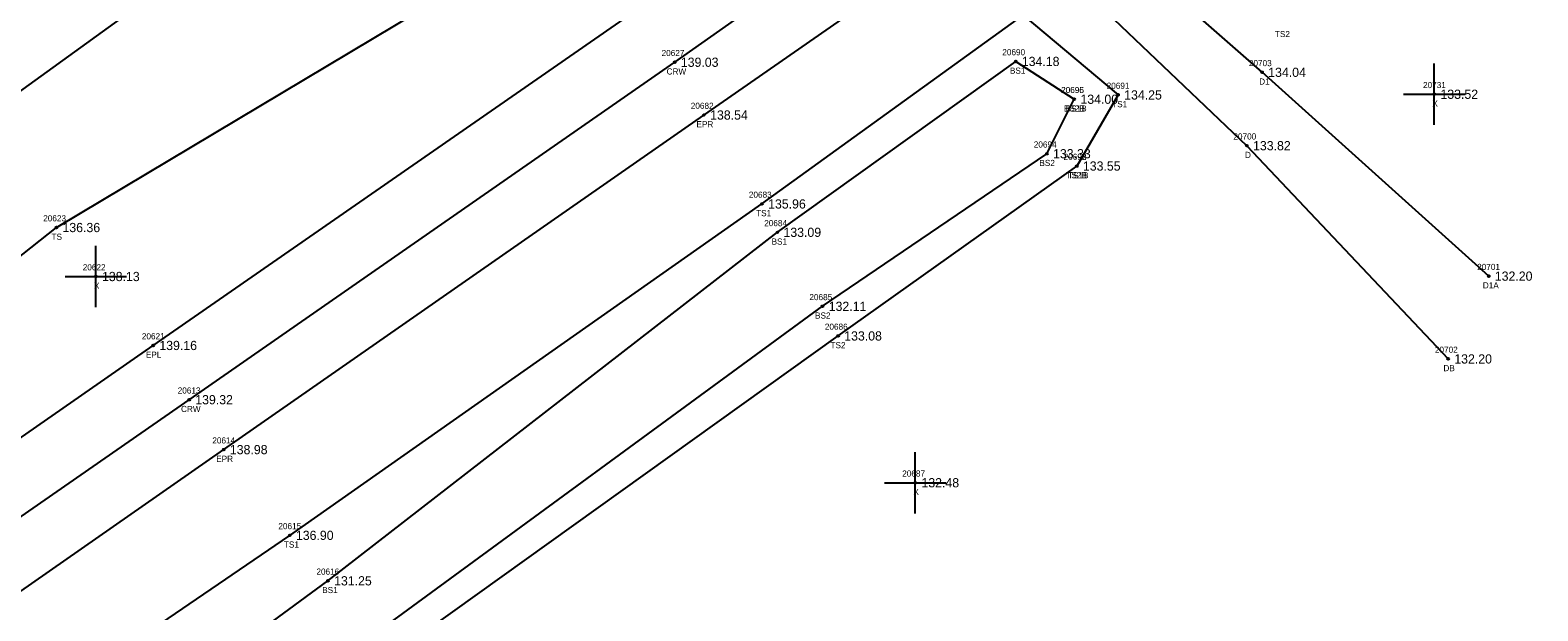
# Model space of a CAD drawing. Extents: x 2449605 to 2452431, y 1012876 to 1014922.
# Drawn here: x 2451655.9 to 2451901.5, y 1014341.9 to 1014436.4 of the extents above; entities that cross this region are included whole.
import ezdxf

# ---------------------------------------------------------------- set-up
doc = ezdxf.new("R2010")
doc.units = 0
for name, color, linetype in [('RD_DTM_BkLn1', 7, 'Continuous'), ('RD_DTM_BkLn2', 7, 'Continuous'), ('RD_DTM_BkLn_txCode', 7, 'Continuous'), ('RD_EX_Driveway', 7, 'Continuous'), ('RD_EX_Driveway_txCode', 7, 'Continuous'), ('RD_EX_Misc', 7, 'Continuous'), ('RD_EX_Misc_txCode', 7, 'Continuous'), ('RD_EX_Road', 7, 'Continuous'), ('RD_EX_Road_txCode', 7, 'Continuous'), ('RD_EX_TX_Driveway_ELEV', 7, 'Continuous'), ('RD_EX_TX_Misc_ELEV', 7, 'Continuous'), ('RD_EX_TX_Road_ELEV', 7, 'Continuous'), ('RD_HC_Survey_ELEV', 7, 'Continuous'), ('RD_HC_Survey_txCode', 7, 'Continuous'), ('RD_SMD_Locator', 7, 'Continuous')]:
    doc.layers.add(name, color=color, linetype=linetype)

msp = doc.modelspace()

# ---------------------------------------------------------------- linework, layer by layer
at = {"layer": 'RD_DTM_BkLn1'}
msp.add_lwpolyline([(2451118.89, 1013985.11), (2451203.66, 1014044.04), (2451282.83, 1014099.78), (2451359.44, 1014152.74), (2451440.83, 1014209.36), (2451521.56, 1014265.18), (2451601.57, 1014320.62), (2451681.76, 1014376.26), (2451760.87, 1014431.18), (2451838.81, 1014486.02), (2451917.14, 1014540.46), (2451997.53, 1014596.52), (2452078.1, 1014652.75), (2452159.13, 1014709.2), (2452240.28, 1014765.75), (2452322.88, 1014822.76), (2452350.66, 1014841.92)], dxfattribs=at)
at = {"layer": 'RD_DTM_BkLn2'}
for points in [[(2451646.62, 1014421.01), (2451727.98, 1014479.74), (2451737.36, 1014488.81), (2451748.87, 1014487.34), (2451780.97, 1014516.03), (2451800.08, 1014516.09), (2451808.87, 1014514.25), (2451815.19, 1014518.52), (2451893.94, 1014584.77), (2451968.95, 1014641.82), (2452055.92, 1014696.27), (2452133.42, 1014744.91), (2452217.68, 1014799.33), (2452300.38, 1014857.1), (2452325.49, 1014877.68)], [(2451585.42, 1014345.19), (2451660.13, 1014404.28), (2451733.72, 1014448.23), (2451745.11, 1014454.23), (2451764.12, 1014467.91), (2451768.27, 1014469.92), (2451766.55, 1014486.31), (2451774.07, 1014492.64), (2451778.81, 1014490.13), (2451790.61, 1014483.42), (2451801.96, 1014488.52), (2451805.7, 1014492.48), (2451808.19, 1014504.09), (2451819.08, 1014511.44), (2451904.04, 1014564.11), (2451984.51, 1014617.35), (2452065.76, 1014673.28), (2452142.48, 1014732.95), (2452225.73, 1014787.51), (2452309.72, 1014842.9), (2452337.15, 1014861.43)], [(2451122.2, 1013975.67), (2451126.64, 1013971.77), (2451133.91, 1013974.2), (2451213.29, 1014028.58), (2451297.97, 1014080.75), (2451370.59, 1014133.41), (2451455.73, 1014187.81), (2451537.96, 1014241.24), (2451616.44, 1014298.53), (2451698.16, 1014354.19), (2451775.09, 1014408.12), (2451817.62, 1014438.82), (2451833.1, 1014425.86), (2451826.37, 1014414.29)], [(2451136.08, 1013956.85), (2451223.22, 1014008.35), (2451307.68, 1014070.02), (2451383.47, 1014112.6), (2451463.99, 1014176.33), (2451545.36, 1014231.17), (2451624.01, 1014287.82), (2451704.38, 1014346.79), (2451777.59, 1014403.5), (2451816.42, 1014431.31), (2451825.97, 1014425.16)], [(2451414.14, 1014133.11), (2451434.24, 1014145.95), (2451469.57, 1014168.89), (2451548.61, 1014225.27), (2451628.95, 1014281.61), (2451710.51, 1014337.03), (2451784.96, 1014391.46), (2451821.51, 1014416.29), (2451825.97, 1014425.16)], [(2451414.14, 1014133.11), (2451438.11, 1014142.38), (2451471.43, 1014164.27), (2451550.48, 1014222.82), (2451631.22, 1014277.79), (2451713.04, 1014333.4), (2451787.49, 1014386.64), (2451826.37, 1014414.29)]]:
    msp.add_lwpolyline(points, dxfattribs=at)
at = {"layer": 'RD_EX_Driveway'}
for points in [[(2451893.48, 1014396.37), (2451856.56, 1014429.54), (2451835.71, 1014447.82), (2451825.17, 1014464.13)], [(2451815.07, 1014456.96), (2451825.59, 1014444.74), (2451854.09, 1014417.6), (2451886.88, 1014382.9)]]:
    msp.add_lwpolyline(points, dxfattribs=at)
at = {"layer": 'RD_EX_Misc'}
for p, q in [((2451884.62, 1014420.97), (2451884.62, 1014430.97)), ((2451879.62, 1014425.97), (2451889.62, 1014425.97)), ((2451666.57, 1014391.31), (2451666.57, 1014401.31)), ((2451661.57, 1014396.31), (2451671.57, 1014396.31)), ((2451800.07, 1014357.75), (2451800.07, 1014367.75)), ((2451795.07, 1014362.75), (2451805.07, 1014362.75))]:
    msp.add_line(p, q, dxfattribs=at)
at = {"layer": 'RD_EX_Road'}
for points in [[(2451113.37, 1013993.22), (2451114.95, 1013995.06), (2451198.45, 1014053.46), (2451277.07, 1014108.71), (2451354.65, 1014162.03), (2451438.1, 1014219.98), (2451516.17, 1014274.12), (2451595.76, 1014329.36), (2451675.91, 1014385.09), (2451754.57, 1014439.6), (2451832.18, 1014494.6), (2451911.27, 1014549.31), (2451991.99, 1014605.1), (2452071.96, 1014661.47), (2452153.31, 1014717.5), (2452234.82, 1014774.14), (2452317.24, 1014831.48), (2452344.94, 1014850.58)], [(2451124.98, 1013977.04), (2451208.96, 1014035.6), (2451289.19, 1014091.86), (2451364.64, 1014143.97), (2451446.58, 1014201.16), (2451526.53, 1014256.42), (2451607.39, 1014312.42), (2451687.4, 1014368.14), (2451765.64, 1014422.59), (2451815.07, 1014456.96), (2451825.17, 1014464.13), (2451844.11, 1014477.45), (2451922.22, 1014531.75), (2452002.87, 1014588.1), (2452083.85, 1014644.47), (2452165.65, 1014701.19), (2452246.96, 1014757.82), (2452328.43, 1014814.34), (2452355.9, 1014833.22)]]:
    msp.add_lwpolyline(points, dxfattribs=at)
at = {"layer": 'RD_SMD_Locator'}
for centre in [(2451760.87, 1014431.18), (2451816.42, 1014431.31), (2451856.56, 1014429.54), (2451825.97, 1014425.16), (2451825.97, 1014425.16), (2451833.1, 1014425.86), (2451884.62, 1014425.97), (2451765.64, 1014422.59), (2451854.09, 1014417.6), (2451821.51, 1014416.29), (2451826.37, 1014414.29), (2451826.37, 1014414.29), (2451775.09, 1014408.12), (2451660.13, 1014404.28), (2451777.59, 1014403.5), (2451666.57, 1014396.31), (2451893.48, 1014396.37), (2451784.96, 1014391.46), (2451675.91, 1014385.09), (2451787.49, 1014386.64), (2451886.88, 1014382.9), (2451681.76, 1014376.26), (2451687.4, 1014368.14), (2451800.07, 1014362.75), (2451698.16, 1014354.19), (2451704.38, 1014346.79)]:
    msp.add_circle(centre, 0.15, dxfattribs=at)

# ---------------------------------------------------------------- texts
at = {"layer": 'RD_DTM_BkLn_txCode'}
for s, p in [('TS2', (2451858.65, 1014435.27)), ('20690', (2451814.24, 1014432.31)), ('BS1', (2451815.48, 1014429.31)), ('20696', (2451823.81, 1014426.16)), ('20695', (2451823.83, 1014426.16)), ('20691', (2451831.24, 1014426.86)), ('TS1', (2451832.14, 1014423.86)), ('BS2B', (2451824.27, 1014423.16)), ('BS1B', (2451824.56, 1014423.16)), ('20694', (2451819.37, 1014417.29)), ('BS2', (2451820.28, 1014414.29)), ('20692', (2451824.23, 1014415.29)), ('20693', (2451824.23, 1014415.29)), ('TS2B', (2451824.65, 1014412.29)), ('TS1B', (2451824.94, 1014412.29)), ('20683', (2451772.95, 1014409.12)), ('20623', (2451657.99, 1014405.28)), ('TS1', (2451774.13, 1014406.12)), ('20684', (2451775.45, 1014404.5)), ('TS', (2451659.34, 1014402.28)), ('BS1', (2451776.65, 1014401.5)), ('20685', (2451782.81, 1014392.46)), ('BS2', (2451783.73, 1014389.46)), ('20686', (2451785.33, 1014387.64)), ('TS2', (2451786.25, 1014384.64)), ('20615', (2451696.3, 1014355.19)), ('TS1', (2451697.2, 1014352.19)), ('20616', (2451702.5, 1014347.79)), ('BS1', (2451703.44, 1014344.79))]:
    msp.add_text(s, height=1, dxfattribs=at).set_placement(p)
at = {"layer": 'RD_EX_Driveway_txCode'}
for s, p in [('20703', (2451854.41, 1014430.54)), ('D1', (2451856.09, 1014427.54)), ('20700', (2451851.89, 1014418.6)), ('D', (2451853.78, 1014415.6)), ('20701', (2451891.6, 1014397.37)), ('D1A', (2451892.52, 1014394.37)), ('20702', (2451884.72, 1014383.9)), ('DB', (2451886.1, 1014380.9))]:
    msp.add_text(s, height=1, dxfattribs=at).set_placement(p)
at = {"layer": 'RD_EX_Misc_txCode'}
for s, p in [('20731', (2451882.78, 1014426.97)), ('X', (2451884.3, 1014423.97)), ('20622', (2451664.43, 1014397.31)), ('X', (2451666.26, 1014394.31)), ('20687', (2451797.93, 1014363.75)), ('X', (2451799.76, 1014360.75))]:
    msp.add_text(s, height=1, dxfattribs=at).set_placement(p)
at = {"layer": 'RD_EX_Road_txCode'}
for s, p in [('20682', (2451763.49, 1014423.59)), ('EPR', (2451764.41, 1014420.59)), ('20621', (2451674.06, 1014386.09)), ('EPL', (2451674.71, 1014383.09)), ('20614', (2451685.54, 1014369.14)), ('EPR', (2451686.17, 1014366.14))]:
    msp.add_text(s, height=1, dxfattribs=at).set_placement(p)
at = {"layer": 'RD_EX_TX_Driveway_ELEV'}
for s, p in [('134.04', (2451857.56, 1014428.79)), ('133.82', (2451855.09, 1014416.85)), ('132.20', (2451894.48, 1014395.62)), ('132.20', (2451887.88, 1014382.15))]:
    msp.add_text(s, height=1.5, dxfattribs=at).set_placement(p)
at = {"layer": 'RD_EX_TX_Misc_ELEV'}
for s, p in [('134.18', (2451817.42, 1014430.56)), ('134.00', (2451826.97, 1014424.41)), ('134.00', (2451826.97, 1014424.41)), ('134.25', (2451834.1, 1014425.11)), ('133.52', (2451885.62, 1014425.22)), ('133.33', (2451822.51, 1014415.54)), ('133.55', (2451827.37, 1014413.54)), ('133.55', (2451827.37, 1014413.54)), ('135.96', (2451776.09, 1014407.37)), ('136.36', (2451661.13, 1014403.53)), ('133.09', (2451778.59, 1014402.75)), ('138.13', (2451667.57, 1014395.56)), ('132.11', (2451785.96, 1014390.71)), ('133.08', (2451788.49, 1014385.89)), ('132.48', (2451801.07, 1014362)), ('136.90', (2451699.16, 1014353.44)), ('131.25', (2451705.38, 1014346.04))]:
    msp.add_text(s, height=1.5, dxfattribs=at).set_placement(p)
at = {"layer": 'RD_EX_TX_Road_ELEV'}
for s, p in [('138.54', (2451766.64, 1014421.84)), ('139.16', (2451676.91, 1014384.34)), ('138.98', (2451688.4, 1014367.39))]:
    msp.add_text(s, height=1.5, dxfattribs=at).set_placement(p)
at = {"layer": 'RD_HC_Survey_ELEV'}
for s, p in [('139.03', (2451761.87, 1014430.43)), ('139.32', (2451682.76, 1014375.51))]:
    msp.add_text(s, height=1.5, dxfattribs=at).set_placement(p)
at = {"layer": 'RD_HC_Survey_txCode'}
for s, p in [('20627', (2451758.73, 1014432.18)), ('CRW', (2451759.55, 1014429.18)), ('20613', (2451679.9, 1014377.26)), ('CRW', (2451680.44, 1014374.26))]:
    msp.add_text(s, height=1, dxfattribs=at).set_placement(p)

doc.saveas('drawing.dxf')
